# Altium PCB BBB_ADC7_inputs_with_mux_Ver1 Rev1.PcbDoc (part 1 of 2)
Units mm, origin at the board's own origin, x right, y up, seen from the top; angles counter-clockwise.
Board outline 219.96 x 100 mm, 2 copper layers (TopLayer, BottomLayer), stack 1.571 mm thick; 181 components, 118 nets, 709 pads, 266 vias.
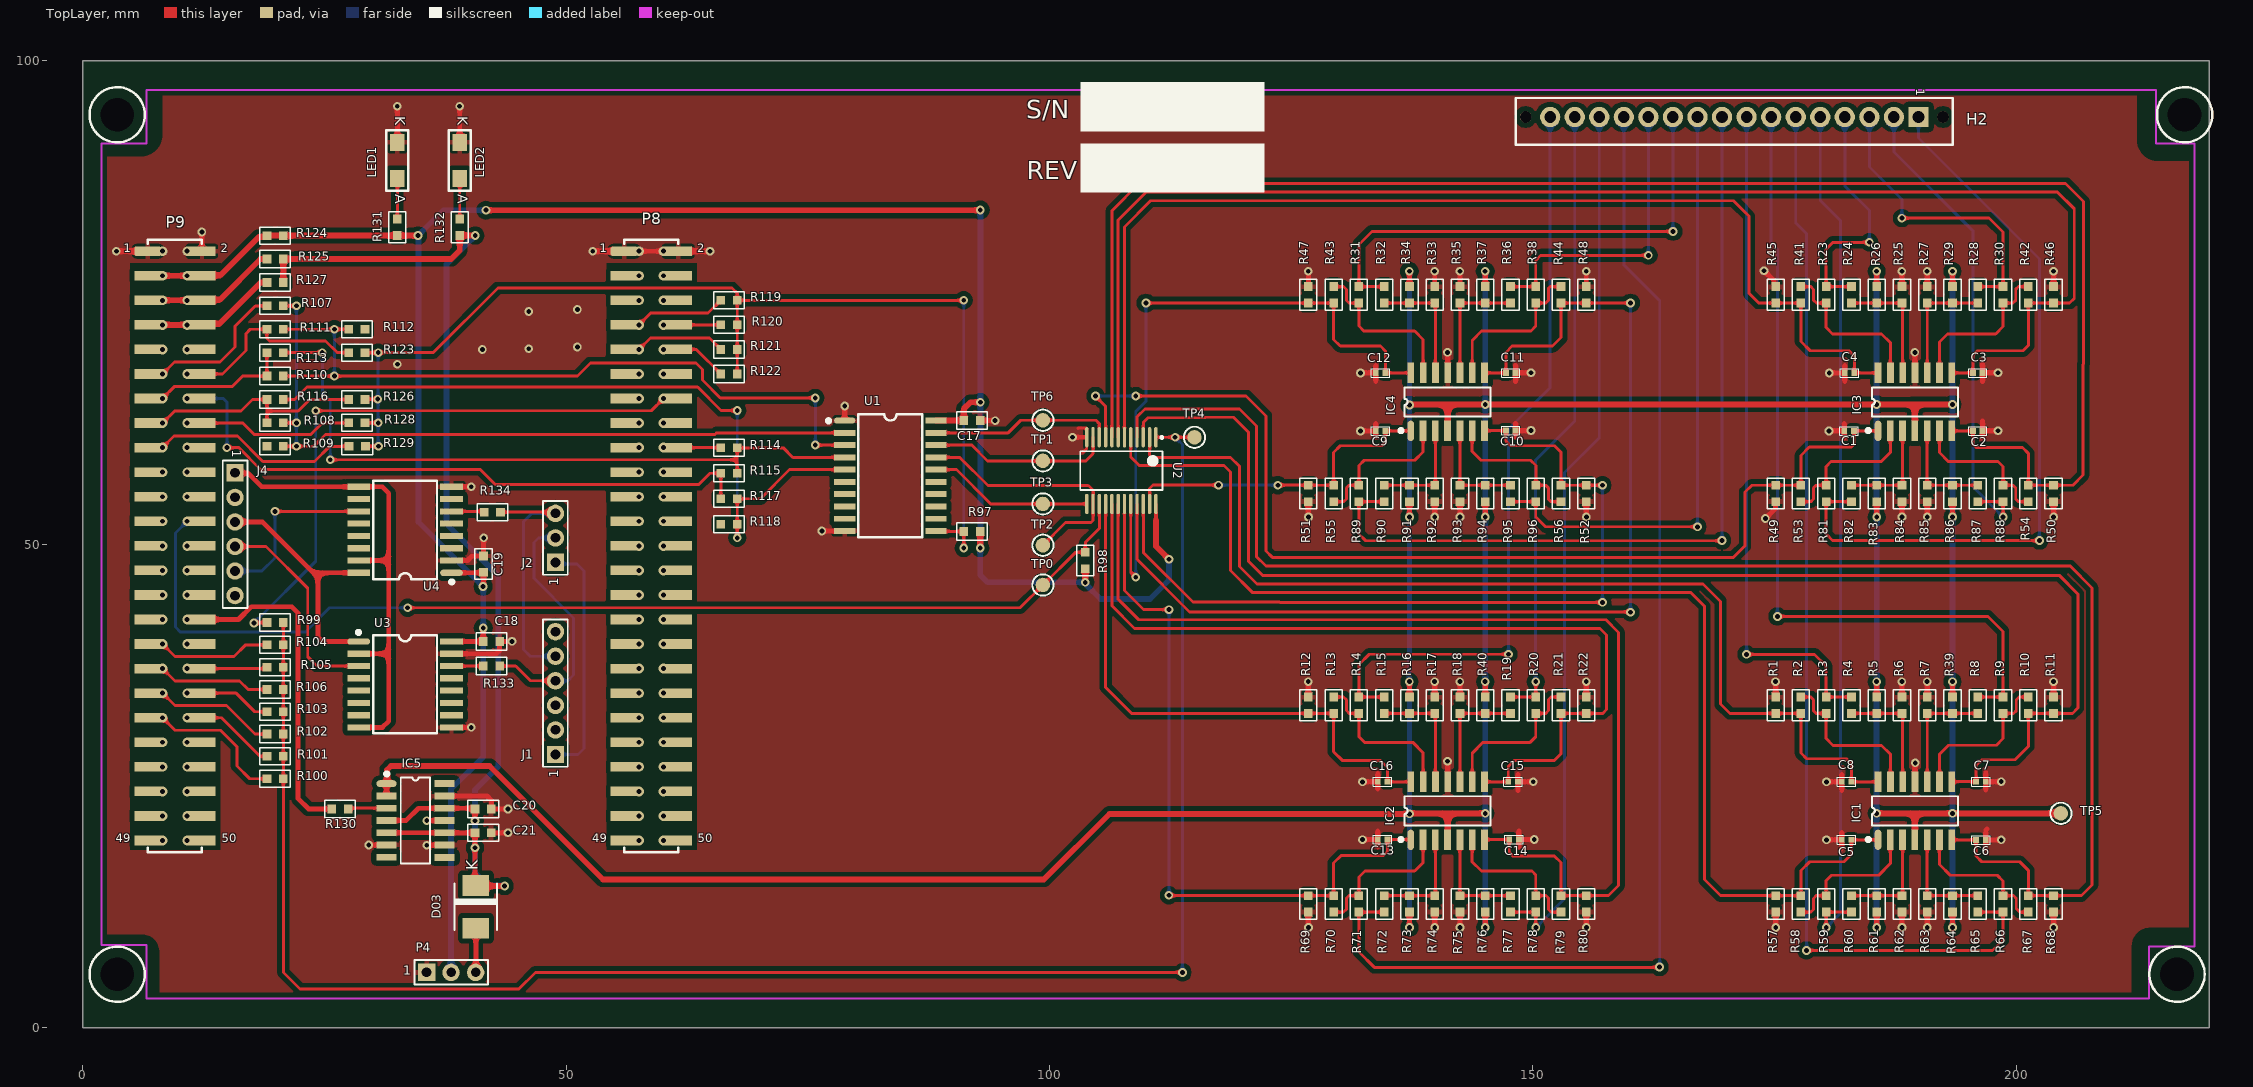
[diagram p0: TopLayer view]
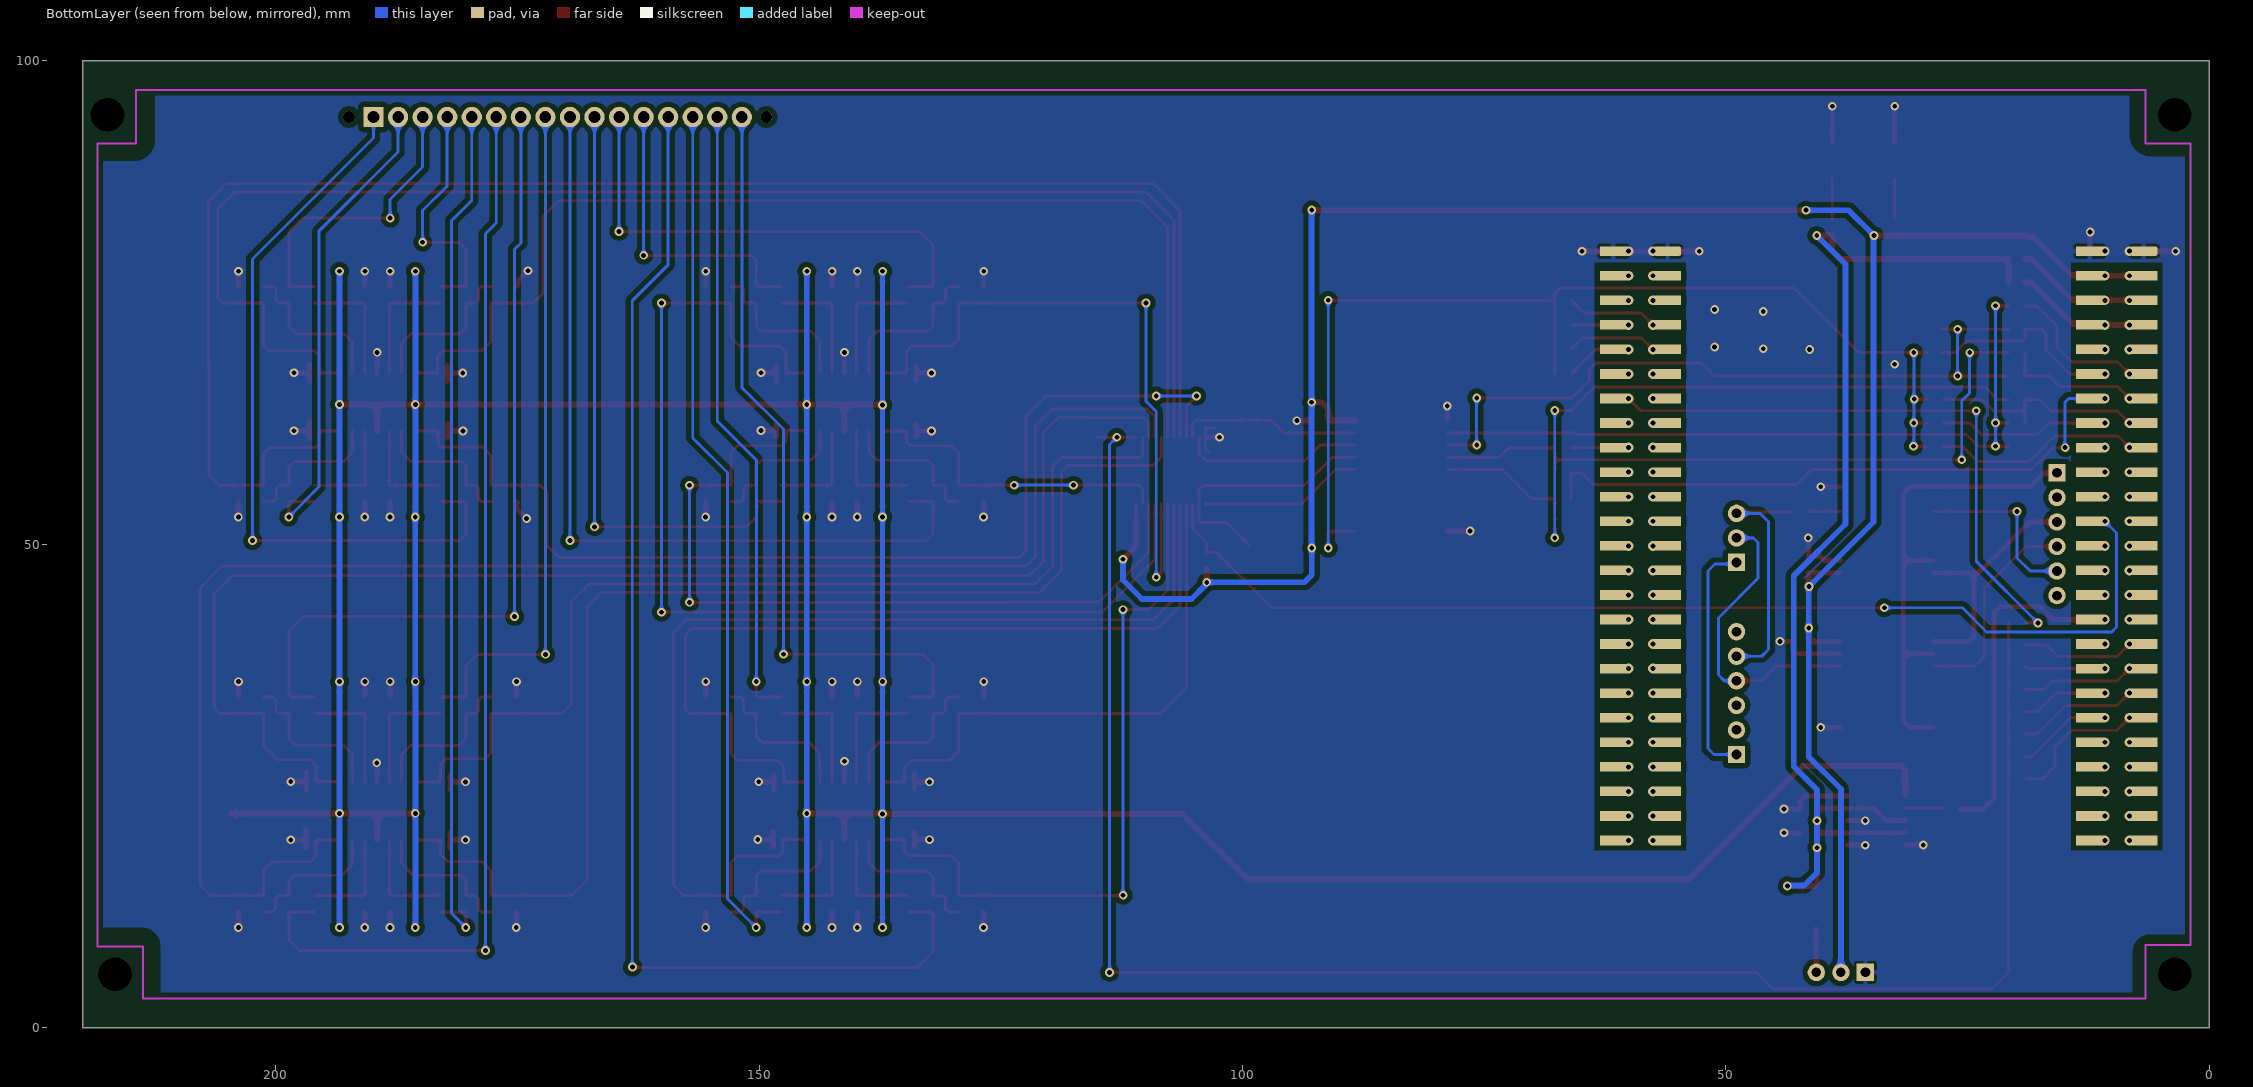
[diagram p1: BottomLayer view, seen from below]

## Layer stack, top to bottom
TopSolder: solder mask 0.0102, Solder Resist, Dk 3.5
TopLayer: signal copper 0.0356
Dielectric1: core 1.5, FR-4, Dk 4.8
BottomLayer: signal copper 0.0356
BottomSolder: solder mask 0.0102, Solder Resist, Dk 3.5

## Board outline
0,0 219.964,0 219.964,100 0,100

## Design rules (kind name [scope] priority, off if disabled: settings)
AssemblyTestPointUsage AssemblyTestPointUsage_1 [All] p2:
AssemblyTestpoint AssemblyTestpoint_1 [All] p2: testpointundercomponent=TRUE minsize=1.016 maxsize=2.54 preferedsize=1.524 minholesize=0 maxholesize=1.016 preferedholesize=0.813 testpointgrid=0.025 usegrid=TRUE gridtolerance=0 allowsidetop=TRUE allowsidebottom=TRUE
Clearance Clearance_1 [All vs InPolygon] p1: gap=0.508 ignorepadtopadclearanceinfootprint=FALSE
Clearance [All] p2: gap=0.254 ignorepadtopadclearanceinfootprint=FALSE
FabricationTestPointUsage TestPointUsage [All] p2: valid=0 allowmultiple=FALSE
FabricationTestpoint Testpoint [All] p2: side=3 testpointundercomponent=TRUE minsize=1.016 maxsize=2.54 preferedsize=1.524 minholesize=0.508 maxholesize=1.016 preferedholesize=0.813 testpointgrid=0.025 allowsidetop=TRUE allowsidebottom=TRUE usegrid=TRUE gridtolerance=0
FanoutControl Fanout_LCC [IsLCC] p1: bgadir=Out bgaviamode=Centered fanoutstyle=Auto fanoutdirection=Alternating viagrid=0.025 // Fanout_LCC (Default Rule)
FanoutControl Fanout_BGA [IsBGA] p2: bgadir=Out bgaviamode=Centered fanoutstyle=Auto fanoutdirection=Alternating viagrid=0.025 // Fanout_BGA (Default Rule)
FanoutControl Fanout_Small [(CompPinCount < 5)] p3: bgadir=Out bgaviamode=Centered fanoutstyle=Auto fanoutdirection=OutThenIn viagrid=0.025 // Fanout_Small (Default Rule)
FanoutControl Fanout_SOIC [IsSOIC] p4: bgadir=Out bgaviamode=Centered fanoutstyle=Auto fanoutdirection=Alternating viagrid=0.025 // Fanout_SOIC (Default Rule)
FanoutControl Fanout_BGA_1 [IsBGA] p6: bgadir=Out bgaviamode=Centered fanoutstyle=Auto fanoutdirection=Alternating viagrid=0.025 // Fanout_BGA (Default Rule)
FanoutControl Fanout_LCC_1 [IsLCC] p7: bgadir=Out bgaviamode=Centered fanoutstyle=Auto fanoutdirection=Alternating viagrid=0.025 // Fanout_LCC (Default Rule)
FanoutControl Fanout_SOIC_1 [IsSOIC] p8: bgadir=Out bgaviamode=Centered fanoutstyle=Auto fanoutdirection=Alternating viagrid=0.025 // Fanout_SOIC (Default Rule)
FanoutControl Fanout_Small_1 [(CompPinCount < 5)] p9: bgadir=Out bgaviamode=Centered fanoutstyle=Auto fanoutdirection=OutThenIn viagrid=0.025 // Fanout_Small (Default Rule)
FanoutControl Fanout_Default_1 [All] p10: bgadir=Out bgaviamode=Centered fanoutstyle=Auto fanoutdirection=Alternating viagrid=0.025 // Fanout_Default (Default Rule)
Height Height_1 [All] p2: minheight=0 maxheight=25.4 prefheight=12.7
HoleSize [All] p1: absolutevalues=TRUE maxlimit=6 minlimit=0.1 maxpercent=80.000 minpercent=20.000
MinimumSolderMaskSliver [All] p1 off: minsoldermaskwidth=0.254
PolygonConnect PolygonConnect_1 [All] p1: thpad.connectstyle=Relief thpad.reliefconductorwidth=0.5 thpad.reliefentries=4 thpad.polygonreliefangle="90 Angle" thpad.airgapwidth=0.254 smdpad.connectstyle=Relief smdpad.reliefconductorwidth=0.5 smdpad.reliefentries=4 smdpad.polygonreliefangle="90 Angle" smdpad.airgapwidth=0.254 via.connectstyle=Direct via.reliefconductorwidth=0.5 via.reliefentries=4 via.polygonreliefangle="90 Angle" via.airgapwidth=0.254
RoutingVias [All] p1: holewidth=0.5 width=0.9 viastyle="Through Hole" minholewidth=0.1 minwidth=0.45 maxholewidth=0.5 maxwidth=0.9
SilkToSilkClearance [All] p1: silktosilkclearance=0.15
SilkToSolderMaskClearance [IsPad] p1 off: minsilkscreentomaskgap=0.254 clearancetoexposedcopper=TRUE
SolderMaskExpansion [All] p1: expansion=0.102
Width [All] p1: maxlimit=5 minlimit=0.15 preferedwidth=0.3
22 further rules are at their usual default settings.

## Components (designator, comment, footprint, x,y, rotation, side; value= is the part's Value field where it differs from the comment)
C1 "CAPACITOR NONPOLAR SMT" C0402 182.718,61.719 r180 top
C2 "CAPACITOR NONPOLAR SMT" C0402 196.025,61.719 r0 top
C3 "CAPACITOR NONPOLAR SMT" C0402 196.025,67.719 r0 top
C4 "CAPACITOR NONPOLAR SMT" C0402 182.756,67.712 r180 top
C5 "CAPACITOR NONPOLAR SMT" C0402 182.456,19.416 r180 top
C6 "CAPACITOR NONPOLAR SMT" C0402 196.356,19.402 r0 top
C7 "CAPACITOR NONPOLAR SMT" C0402 196.356,25.428 r0 top
C8 "CAPACITOR NONPOLAR SMT" C0402 182.456,25.416 r180 top
C9 "CAPACITOR NONPOLAR SMT" C0402 134.256,61.712 r180 top
C10 "CAPACITOR NONPOLAR SMT" C0402 147.714,61.748 r0 top
C11 "CAPACITOR NONPOLAR SMT" C0402 147.714,67.719 r0 top
C12 "CAPACITOR NONPOLAR SMT" C0402 134.256,67.719 r180 top
C13 "CAPACITOR NONPOLAR SMT" C0402 134.462,19.444 r180 top
C14 "CAPACITOR NONPOLAR SMT" C0402 148.056,19.444 r0 top
C15 "CAPACITOR NONPOLAR SMT" C0402 147.956,25.416 r0 top
C16 "CAPACITOR NONPOLAR SMT" C0402 134.462,25.416 r180 top
C17 "4.7uF, 10V" C0603 91.985,62.788 r0 top
C18 "4.7uF, 10V" C0603 42.266,39.929 r0 top
C19 "4.7uF, 10V" C0603 41.456,47.932 r90 top
C20 "100nF" C0603 41.416,22.606 r0 top
C21 "4.7uF / 10V" C0603 41.416,20.137 r0 top
D03 "1.5A, PIV 1KV" DIODE_DO-214AA(SMB) 40.665,12.471 r90 top
H2 "connector 16 pin male_ stright" "16 PIN MALE STRIGHT" 170.84,94.183 r180 top
IC1 "OPamp" SOIC-14 189.522,22.416 r0 top
IC2 "OPamp" SOIC-14 141.186,22.416 r0 top
IC3 "OPamp" SOIC-14 189.522,64.719 r0 top
IC4 "OPamp" SOIC-14 141.186,64.719 r0 top
IC5 "OPamp" SOIC-14 34.417,21.412 r270 top
J1 "Header 6" HDR1X6 48.895,28.245 r90 top
J2 "Header 3" HDR1X3 48.895,48.108 r90 top
J4 "Header 6" HDR1X6 15.748,57.379 r270 top locked
LED1 "LED" "0537, LED, 1206" 32.537,89.687 r270 top
LED2 "LED" "0537, LED, 1206" 38.996,89.687 r270 top
P4 "Header 3" HDR1X3 35.56,5.703 r0 top
P8 "Header 20X2" BBBHEADERNOHOLE 58.801,79.035 r180 top locked
P9 "Header 20X2" BBBHEADERNOHOLE 9.525,79.035 r180 top locked
R1 "Resistor SMD 0603, 100 k Ohm, +/-5%, 1/10W" 0603 175.114,33.338 r90 top
R2 "Resistor SMD 0603, 1.5 k Ohm, +/-5%, 1/10W" 0603 177.728,33.338 r90 top
R3 "Resistor SMD 0603, 9.1 k Ohm, +/-5%, 1/10W" 0603 180.342,33.338 r90 top
R4 "open" 0603 182.956,33.338 r90 top
R5 "Resistor SMD 0603, 6.8 k Ohm, +/-1%, 1/10W" 0603 185.57,33.338 r90 top
R6 "Resistor SMD 0603, 4.7 k Ohm, +/-5%, 1/10W" 0603 188.183,33.338 r90 top
R7 "Resistor SMD 0603, 4.7 k Ohm, +/-5%, 1/10W" 0603 190.797,33.338 r90 top
R8 "open" 0603 196.025,33.338 r90 top
R9 "Resistor SMD 0603, 9.1 k Ohm, +/-5%, 1/10W" 0603 198.639,33.338 r270 top
R10 "Resistor SMD 0603, 1.5 k Ohm, +/-5%, 1/10W" 0603 201.253,33.338 r90 top
R11 "Resistor SMD 0603, 100 k Ohm, +/-5%, 1/10W" 0603 203.867,33.338 r90 top
R12 "Resistor SMD 0603, 100 k Ohm, +/-5%, 1/10W" 0603 126.778,33.338 r90 top
R13 "Resistor SMD 0603, 1.5 k Ohm, +/-5%, 1/10W" 0603 129.391,33.338 r90 top
R14 "Resistor SMD 0603, 9.1 k Ohm, +/-5%, 1/10W" 0603 132.005,33.338 r90 top
R15 "open" 0603 134.619,33.338 r90 top
R16 "Resistor SMD 0603, 6.8 k Ohm, +/-1%, 1/10W" 0603 137.233,33.338 r90 top
R17 "Resistor SMD 0603, 4.7 k Ohm, +/-5%, 1/10W" 0603 139.847,33.338 r90 top
R18 "Resistor SMD 0603, 4.7 k Ohm, +/-5%, 1/10W" 0603 142.461,33.338 r90 top
R19 "open" 0603 147.689,33.338 r90 top
R20 "Resistor SMD 0603, 9.1 k Ohm, +/-5%, 1/10W" 0603 150.303,33.338 r270 top
R21 "Resistor SMD 0603, 1.5 k Ohm, +/-5%, 1/10W" 0603 152.916,33.338 r90 top
R22 "Resistor SMD 0603, 100 k Ohm, +/-5%, 1/10W" 0603 155.53,33.338 r90 top
R23 "Resistor SMD 0603, 9.1 k Ohm, +/-5%, 1/10W" 0603 180.342,75.794 r90 top
R24 "OPEN" 0603 182.956,75.794 r90 top
R25 "Resistor SMD 0603, 4.7 k Ohm, +/-5%, 1/10W" 0603 188.183,75.794 r90 top
R26 "Resistor SMD 0603, 6.8 k Ohm, +/-1%, 1/10W" 0603 185.57,75.794 r90 top
R27 "Resistor SMD 0603, 4.7 k Ohm, +/-5%, 1/10W" 0603 190.797,75.794 r90 top
R28 "OPEN" 0603 196.025,75.794 r90 top
R29 "Resistor SMD 0603, 6.8 k Ohm, +/-1%, 1/10W" 0603 193.411,75.794 r90 top
R30 "Resistor SMD 0603, 9.1 k Ohm, +/-5%, 1/10W" 0603 198.639,75.794 r270 top
R31 "Resistor SMD 0603, 9.1 k Ohm, +/-5%, 1/10W" 0603 132.005,75.794 r90 top
R32 "OPEN" 0603 134.619,75.794 r90 top
R33 "Resistor SMD 0603, 4.7 k Ohm, +/-5%, 1/10W" 0603 139.847,75.794 r90 top
R34 "Resistor SMD 0603, 6.8 k Ohm, +/-1%, 1/10W" 0603 137.233,75.794 r90 top
R35 "Resistor SMD 0603, 4.7 k Ohm, +/-5%, 1/10W" 0603 142.461,75.794 r90 top
R36 "OPEN" 0603 147.689,75.794 r90 top
R37 "Resistor SMD 0603, 6.8 k Ohm, +/-1%, 1/10W" 0603 145.075,75.794 r90 top
R38 "Resistor SMD 0603, 9.1 k Ohm, +/-5%, 1/10W" 0603 150.303,75.794 r270 top
R39 "Resistor SMD 0603, 6.8 k Ohm, +/-1%, 1/10W" 0603 193.411,33.338 r90 top
R40 "Resistor SMD 0603, 6.8 k Ohm, +/-1%, 1/10W" 0603 145.075,33.338 r90 top
R41 "Resistor SMD 0603, 1.5 k Ohm, +/-5%, 1/10W" 0603 177.728,75.794 r90 top
R42 "Resistor SMD 0603, 1.5 k Ohm, +/-5%, 1/10W" 0603 201.253,75.794 r270 top
R43 "Resistor SMD 0603, 1.5 k Ohm, +/-5%, 1/10W" 0603 129.391,75.794 r90 top
R44 "Resistor SMD 0603, 1.5 k Ohm, +/-5%, 1/10W" 0603 152.916,75.794 r270 top
R45 "Resistor SMD 0603, 100 k Ohm, +/-5%, 1/10W" 0603 175.114,75.794 r90 top
R46 "Resistor SMD 0603, 100 k Ohm, +/-5%, 1/10W" 0603 203.867,75.794 r90 top
R47 "Resistor SMD 0603, 100 k Ohm, +/-5%, 1/10W" 0603 126.778,75.794 r90 top
R48 "Resistor SMD 0603, 100 k Ohm, +/-5%, 1/10W" 0603 155.53,75.794 r90 top
R49 "Resistor SMD 0603, 100 k Ohm, +/-5%, 1/10W" 0603 175.114,55.245 r270 top
R50 "Resistor SMD 0603, 100 k Ohm, +/-5%, 1/10W" 0603 203.867,55.245 r270 top
R51 "Resistor SMD 0603, 100 k Ohm, +/-5%, 1/10W" 0603 126.778,55.245 r270 top
R52 "Resistor SMD 0603, 100 k Ohm, +/-5%, 1/10W" 0603 155.53,55.245 r270 top
R53 "Resistor SMD 0603, 1.5 k Ohm, +/-5%, 1/10W" 0603 177.728,55.245 r270 top
R54 "Resistor SMD 0603, 1.5 k Ohm, +/-5%, 1/10W" 0603 201.253,55.245 r90 top
R55 "Resistor SMD 0603, 1.5 k Ohm, +/-5%, 1/10W" 0603 129.391,55.245 r270 top
R56 "Resistor SMD 0603, 1.5 k Ohm, +/-5%, 1/10W" 0603 152.916,55.245 r90 top
R57 "Resistor SMD 0603, 100 k Ohm, +/-5%, 1/10W" 0603 175.114,12.789 r90 top
R58 "Resistor SMD 0603, 1.5 k Ohm, +/-5%, 1/10W" 0603 177.728,12.789 r90 top
R59 "Resistor SMD 0603, 9.1 k Ohm, +/-5%, 1/10W" 0603 180.342,12.789 r90 top
R60 "open" 0603 182.956,12.789 r90 top
R61 "Resistor SMD 0603, 6.8 k Ohm, +/-1%, 1/10W" 0603 185.57,12.789 r90 top
R62 "Resistor SMD 0603, 4.7 k Ohm, +/-5%, 1/10W" 0603 188.183,12.789 r90 top
R63 "Resistor SMD 0603, 4.7 k Ohm, +/-5%, 1/10W" 0603 190.797,12.789 r90 top
R64 "Resistor SMD 0603, 6.8 k Ohm, +/-1%, 1/10W" 0603 193.411,12.789 r90 top
R65 "open" 0603 196.025,12.789 r90 top
R66 "Resistor SMD 0603, 9.1 k Ohm, +/-5%, 1/10W" 0603 198.639,12.789 r90 top
R67 "Resistor SMD 0603, 1.5 k Ohm, +/-5%, 1/10W" 0603 201.253,12.789 r270 top
R68 "Resistor SMD 0603, 100 k Ohm, +/-5%, 1/10W" 0603 203.867,12.789 r270 top
R69 "Resistor SMD 0603, 100 k Ohm, +/-5%, 1/10W" 0603 126.778,12.789 r90 top
R70 "Resistor SMD 0603, 1.5 k Ohm, +/-5%, 1/10W" 0603 129.391,12.789 r90 top
R71 "Resistor SMD 0603, 9.1 k Ohm, +/-5%, 1/10W" 0603 132.005,12.789 r90 top
R72 "open" 0603 134.619,12.789 r90 top
R73 "Resistor SMD 0603, 6.8 k Ohm, +/-1%, 1/10W" 0603 137.233,12.789 r90 top
R74 "Resistor SMD 0603, 4.7 k Ohm, +/-5%, 1/10W" 0603 139.847,12.789 r90 top
R75 "Resistor SMD 0603, 4.7 k Ohm, +/-5%, 1/10W" 0603 142.461,12.789 r90 top
R76 "Resistor SMD 0603, 6.8 k Ohm, +/-1%, 1/10W" 0603 145.075,12.789 r90 top
R77 "open" 0603 147.689,12.789 r90 top
R78 "Resistor SMD 0603, 9.1 k Ohm, +/-5%, 1/10W" 0603 150.303,12.789 r90 top
R79 "Resistor SMD 0603, 1.5 k Ohm, +/-5%, 1/10W" 0603 152.916,12.789 r270 top
R80 "Resistor SMD 0603, 100 k Ohm, +/-5%, 1/10W" 0603 155.53,12.789 r270 top
R81 "Resistor SMD 0603, 9.1 k Ohm, +/-5%, 1/10W" 0603 180.342,55.245 r90 top
R82 "OPEN" 0603 182.956,55.245 r90 top
R83 "Resistor SMD 0603, 6.8 k Ohm, +/-1%, 1/10W" 0603 185.57,55.245 r90 top
R84 "Resistor SMD 0603, 4.7 k Ohm, +/-5%, 1/10W" 0603 188.183,55.245 r90 top
R85 "Resistor SMD 0603, 4.7 k Ohm, +/-5%, 1/10W" 0603 190.797,55.245 r90 top
R86 "Resistor SMD 0603, 6.8 k Ohm, +/-1%, 1/10W" 0603 193.411,55.245 r90 top
R87 "OPEN" 0603 196.025,55.245 r90 top
R88 "Resistor SMD 0603, 9.1 k Ohm, +/-5%, 1/10W" 0603 198.639,55.245 r90 top
R89 "Resistor SMD 0603, 9.1 k Ohm, +/-5%, 1/10W" 0603 132.005,55.245 r90 top
R90 "OPEN" 0603 134.619,55.245 r90 top
R91 "Resistor SMD 0603, 6.8 k Ohm, +/-1%, 1/10W" 0603 137.233,55.245 r90 top
R92 "Resistor SMD 0603, 4.7 k Ohm, +/-5%, 1/10W" 0603 139.847,55.245 r90 top
R93 "Resistor SMD 0603, 4.7 k Ohm, +/-5%, 1/10W" 0603 142.461,55.245 r90 top
R94 "Resistor SMD 0603, 6.8 k Ohm, +/-1%, 1/10W" 0603 145.075,55.245 r90 top
R95 "OPEN" 0603 147.689,55.245 r90 top
R96 "Resistor SMD 0603, 9.1 k Ohm, +/-5%, 1/10W" 0603 150.303,55.245 r90 top
R97 "" 0603 91.985,51.317 r0 top
R98 "1Kohm" 0603 103.705,48.314 r270 top
R99 "1Kohm" 0603 19.896,41.894 r0 top
R100 "1Kohm" 0603 19.896,25.736 r0 top
R101 "1Kohm" 0603 19.896,28.045 r0 top
R102 "1Kohm" 0603 19.896,30.353 r0 top
R103 "1Kohm" 0603 19.896,32.661 r0 top
R104 "1Kohm" 0603 19.896,39.586 r0 top
R105 "1Kohm" 0603 19.896,37.277 r0 top
R106 "1Kohm" 0603 19.896,34.969 r0 top
R107 "" 0603 19.896,74.651 r0 top
R108 "" 0603 19.896,62.543 r0 top
R109 "" 0603 19.896,60.122 r0 top
R110 "" 0603 19.896,67.386 r0 top
R111 "" 0603 19.896,72.229 r0 top
R112 "" 0603 28.35,72.229 r180 top
R113 "" 0603 19.896,69.808 r0 top
R114 "" 0603 66.853,59.965 r0 top
R115 "" 0603 66.853,57.333 r0 top
R116 "" 0603 19.896,64.965 r0 top
R117 "" 0603 66.853,54.702 r0 top
R118 "" 0603 66.853,52.07 r0 top
R119 "1Kohm" 0603 66.853,75.225 r180 top
R120 "1Kohm" 0603 66.853,72.685 r180 top
R121 "1Kohm" 0603 66.853,70.145 r180 top
R122 "1Kohm" 0603 66.853,67.605 r180 top
R123 "1Kohm" 0603 28.35,69.808 r180 top
R124 "Resistor SMD 0603, 0 Ohm, +/-5%, 1/10W" 0603 19.896,81.915 r0 top
R125 "Resistor SMD 0603, 0 Ohm, +/-5%, 1/10W" 0603 19.896,79.494 r180 top
R126 "1Kohm" 0603 28.35,64.965 r180 top
R127 "Resistor SMD 0603, 0 Ohm, +/-5%, 1/10W" 0603 19.896,77.072 r180 top
R128 "1Kohm" 0603 28.35,62.543 r180 top
R129 "1Kohm" 0603 28.386,60.122 r180 top
R130 "Resistor SMD 0603, 0 Ohm, +/-5%, 1/10W" 0603 26.594,22.606 r0 top
R131 "Resistor SMD 0603, 4.7 k Ohm, +/-5%, 1/10W" 0603 32.537,82.779 r270 top
R132 "Resistor SMD 0603, 4.7 k Ohm, +/-5%, 1/10W" 0603 38.996,82.779 r270 top
R133 "Resistor SMD 0603, 0 Ohm, +/-5%, 1/10W" 0603 42.266,37.389 r0 top
R134 "Resistor SMD 0603, 0 Ohm, +/-5%, 1/10W" 0603 42.367,53.315 r0 top
TP0 "TEST PAD" TP 99.316,45.775 r0 top
TP1 "TEST PAD" TP 99.316,58.609 r0 top
TP2 "TEST PAD" TP 99.316,49.887 r0 top
TP3 "TEST PAD" TP 99.316,54.159 r0 top
TP4 "TEST PAD" TP 114.998,61.046 r0 top
TP5 "TEST PAD" TP 204.625,22.15 r180 top
TP6 "TEST PAD" TP 99.316,62.816 r0 top
U1 "74ACT573SJ" SOL-20 83.538,57.073 r0 top
U2 "4067" SSOP-24 107.43,57.609 r270 top
U3 "ISO7640" SOIC-16 33.339,35.484 r270 top
U4 "ISO7640" SOIC-16 33.339,51.486 r90 top

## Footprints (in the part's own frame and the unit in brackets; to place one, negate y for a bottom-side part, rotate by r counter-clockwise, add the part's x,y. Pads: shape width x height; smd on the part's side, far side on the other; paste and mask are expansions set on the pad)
"16 PIN MALE STRIGHT" [mm]
  round 1.2 hole 1.2 unplated: 0(-21.59,0) 0(21.59,0)
  rect 2.1x2.1 hole 1.2: 1(-19.05,0)
  round 2.1 hole 1.2: 2(-16.51,0) 3(-13.97,0) 4(-11.43,0) 5(-8.89,0) 6(-6.35,0) 7(-3.81,0) 8(-1.27,0) 9(1.27,0) 10(3.81,0) 11(6.35,0) 12(8.89,0) 13(11.43,0) 14(13.97,0) 15(16.51,0) 16(19.05,0)
  silkscreen extent -22.61,-1.97 22.61,2.88, body extent -22.58,-1.96 22.65,2.89, height 7.1
"0537, LED, 1206" [mm]
  rect 1.75x1.5 smd: A(1.875,0) K(-1.875,0)
  silkscreen extent -3.11,-1.14 3.14,1.12, body extent -1.6,-0.8 1.6,0.8, height 1.52
0603 [mm]
  rect 0.9x0.9 smd: 1(-0.85,0) 2(0.85,0)
  silkscreen extent -1.59,-0.89 1.59,0.89, body extent -0.85,-0.4 0.85,0.4, height 0.56
BBBHEADERNOHOLE [mm]
  rrect50% 2.8x1 smd far side: 1(2.77,-1.27)
  rrect50% 2.8x1 smd: 1(2.8,-1.27)
  rect 2.8x1 smd far side: 2(-2.83,-1.27) 3(2.77,1.27) 4(-2.83,1.27) 5(2.77,3.81) 6(-2.83,3.81) 7(2.77,6.35) 8(-2.83,6.35) 9(2.77,8.89) 10(-2.83,8.89) 11(2.77,11.43) 12(-2.83,11.43) 13(2.77,13.97) 14(-2.83,13.97) 15(2.77,16.51) 16(-2.83,16.51) 17(2.77,19.05) 18(-2.83,19.05) 19(2.77,21.59) 20(-2.83,21.59) 21(2.77,24.13) 22(-2.83,24.13) 23(2.77,26.67) 24(-2.83,26.67) 25(2.77,29.21) 26(-2.83,29.21) 27(2.77,31.75) 28(-2.83,31.75) 29(2.77,34.29) 30(-2.83,34.29) 31(2.77,36.83) 32(-2.83,36.83) 33(2.77,39.37) 34(-2.83,39.37) 35(2.77,41.91) 36(-2.83,41.91) 37(2.77,44.45) 38(-2.83,44.45) 39(2.77,46.99) 40(-2.83,46.99) 41(2.77,49.53) 42(-2.83,49.53) 43(2.77,52.07) 44(-2.83,52.07) 45(2.77,54.61) 46(-2.83,54.61) 47(2.77,57.15) 48(-2.83,57.15) 49(2.77,59.69) 50(-2.83,59.69)
  rect 2.8x1 smd: 2(-2.8,-1.27) 3(2.8,1.27) 4(-2.8,1.27) 5(2.8,3.81) 6(-2.8,3.81) 7(2.8,6.35) 8(-2.8,6.35) 9(2.8,8.89) 10(-2.8,8.89) 11(2.8,11.43) 12(-2.8,11.43) 13(2.8,13.97) 14(-2.8,13.97) 15(2.8,16.51) 16(-2.8,16.51) 17(2.8,19.05) 18(-2.8,19.05) 19(2.8,21.59) 20(-2.8,21.59) 21(2.8,24.13) 22(-2.8,24.13) 23(2.8,26.67) 24(-2.8,26.67) 25(2.8,29.21) 26(-2.8,29.21) 27(2.8,31.75) 28(-2.8,31.75) 29(2.8,34.29) 30(-2.8,34.29) 31(2.8,36.83) 32(-2.8,36.83) 33(2.8,39.37) 34(-2.8,39.37) 35(2.8,41.91) 36(-2.8,41.91) 37(2.8,44.45) 38(-2.8,44.45) 39(2.8,46.99) 40(-2.8,46.99) 41(2.8,49.53) 42(-2.8,49.53) 43(2.8,52.07) 44(-2.8,52.07) 45(2.8,54.61) 46(-2.8,54.61) 47(2.8,57.15) 48(-2.8,57.15) 49(2.8,59.69) 50(-2.8,59.69)
  silkscreen extent -2.79,-2.46 2.81,60.88
C0402 [mm] "C0402"
  rect 0.6x0.6 smd: 1(-0.5,0) 2(0.5,0)
  silkscreen extent -0.95,-0.45 0.95,0.45, body extent -0.51,-0.25 0.51,0.25, height 0.51
C0603 [mm]
  rect 0.9x0.9 smd: 1(-0.85,0) 2(0.85,0)
  silkscreen extent -1.59,-0.89 1.59,0.89, body extent -0.8,-0.4 0.8,0.4, height 0.3
DIODE_DO-214AA(SMB) [mm]
  rect 2.159x2.743 smd: 1(-2.21,0) 2(2.21,0)
  silkscreen extent -2.41,-2.2 2.42,2.2, body extent -2.75,-1.95 2.75,1.95, height 2.45
HDR1X3 [mm]
  rect 1.8x1.8 hole 1: 1(0,0)
  round 1.8 hole 1: 2(2.54,0) 3(5.08,0)
  silkscreen extent -1.27,-1.27 6.35,1.27, body extent -1.24,-1.22 6.38,1.32, height 9.07
HDR1X6 [mm] "Connector; Header; 6 Position"
  rect 1.8x1.8 hole 1: 1(0,0)
  round 1.8 hole 1: 2(2.54,0) 3(5.08,0) 4(7.62,0) 5(10.16,0) 6(12.7,0)
  silkscreen extent -1.27,-1.27 13.97,1.27, body extent -1.27,-1.27 13.97,1.27, height 9.07
SOIC-14 [mm]
  oval 0.7x2.1 smd: 1(-3.815,-3)
  rect 0.7x2.1 smd: 2(-2.545,-3) 3(-1.275,-3) 4(-0.005,-3) 5(1.265,-3) 6(2.535,-3) 7(3.805,-3) 8(3.815,3) 9(2.545,3) 10(1.275,3) 11(0.005,3) 12(-1.265,3) 13(-2.535,3) 14(-3.815,3)
  silkscreen extent -4.95,-3.09 4.44,1.51, body extent -4.35,-3.07 4.35,3.07, height 1.88
SOIC-16 [mm]
  oval 0.64x2.35 smd: 1(-4.445,-4.8)
  rect 0.64x2.35 smd: 2(-3.175,-4.8) 3(-1.905,-4.8) 4(-0.635,-4.8) 5(0.635,-4.8) 6(1.905,-4.8) 7(3.175,-4.8) 8(4.445,-4.8) 9(4.445,4.8) 10(3.175,4.8) 11(1.905,4.8) 12(0.635,4.8) 13(-0.635,4.8) 14(-1.905,4.8) 15(-3.175,4.8) 16(-4.445,4.8)
  silkscreen extent -5.51,-4.94 5.05,3.3, body extent -5.17,-5.15 5.16,5.16, height 2.48
SOL-20 [mm]
  oval 2.2x0.61 smd: 1(-4.726,5.715)
  rect 2.2x0.61 smd: 2(-4.726,4.445) 3(-4.726,3.175) 4(-4.726,1.905) 5(-4.726,0.635) 6(-4.726,-0.635) 7(-4.726,-1.905) 8(-4.726,-3.175) 9(-4.726,-4.445) 10(-4.726,-5.715) 11(4.726,-5.715) 12(4.726,-4.445) 13(4.726,-3.175) 14(4.726,-1.905) 15(4.726,-0.635) 16(4.726,0.635) 17(4.726,1.905) 18(4.726,3.175) 19(4.726,4.445) 20(4.726,5.715)
  silkscreen extent -6.51,-6.35 3.3,6.35
SSOP-24 [mm]
  oval 2.1x0.35 smd: 1(-3.45,3.575) 2(-3.45,2.925) 3(-3.45,2.275) 4(-3.45,1.625) 5(-3.45,0.975) 6(-3.45,0.325) 7(-3.45,-0.325) 8(-3.45,-0.975) 9(-3.45,-1.625) 10(-3.45,-2.275) 11(-3.45,-2.925) 12(-3.45,-3.575) 13(3.45,-3.575) 14(3.45,-2.925) 15(3.45,-2.275) 16(3.45,-1.625) 17(3.45,-0.975) 18(3.45,-0.325) 19(3.45,0.325) 20(3.45,0.975) 21(3.45,1.625) 22(3.45,2.275) 23(3.45,2.925) 24(3.45,3.575)
  silkscreen extent -3.56,-4.25 2,4.31, body extent -2.8,-4.25 2.8,4.25, height 2
TP [mm]
  round 1.5 smd paste-2: 1(0,0)
  silkscreen extent -1.1,-1.1 1.1,1.1

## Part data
C1 C2 C3 C4 C5 C6 C7 C8 C9 C10 C11 C12 C13 C14 C15 C16: library part BCS22A-102, "Capacitor ceramic, SMD 0402, 1 nF, +/-10%, 50 V dc", Capacitance=1, Dielectric=X7R, Mfr Name=YAGEO, Package=0402, Tolerance (%)=+/-10%, Units of Capacitance=nF, Units of Voltage="V dc", Value(Farad)=1n, Voltage Rating=50
C17 C18 C19 C21: library part BCS129-475, "Capacitor ceramic, SMD 0603, 4.7 uF, +/-10%, 10 V dc", Capacitance=4.7, Dielectric=X5R, Mfr Name=KEMET, Package=0603, Tolerance (%)=+/-10%, Units of Capacitance=uF, Units of Voltage="V dc", Voltage Rating=10
C20: library part BCS129-104, "Capacitor ceramic, SMD 0603, 100 nF, +/-10%, 16 V dc", Capacitance=100, Dielectric=X7R, Mfr Name=KEMET, Package=0603, Tolerance (%)=+/-10%, Units of Capacitance=nF, Units of Voltage="V dc", Value(Farad)=100n, Voltage Rating=16
D03: library part BDS334-001, "Diode high voltage, SMD DO-214AA, If 1.5 A, PIV 1 kV", Average Forward Current=1.5, Mfr Name=VISHAY, Package=DO-214AA, PackageDocument=Sep-1996, Peak Inverse Voltage=1, Units of Current=A, Units of Voltage=kV
IC1 IC2 IC3 IC4: SMLPARTNO=BIS114-020
IC5: SMLPPARTNO=BIS114-020
J1 J4: "Header, 6-Pin"
J2 P4: "Header, 3-Pin"
LED1 LED2: library part BDS461-001, "Optoelectronic LED, SMD 1206, red colour", LED Colour=Red, Mfr Name="AVAGO TECHNOLOGIES", Package=1206
P8 P9: "Header, 20-Pin, Dual row"
R1 R11 R12 R22 R45 R46 R47 R48 R49 R50 R51 R52 R57 R68 R69 R80: library part BRS133-473, Mfr Name=VISHAY, Package=0603, Power Rating=1/10W, SMLPARTNO=BRS131-104, Tempco1=0.0002, Tolerance=+/-5%, Unit Of Resistance="k Ohm", Value(ohm)=100
R2 R13 R41 R42 R43 R44 R53 R54 R55 R56 R58 R67 R70 R79: library part BRS133-473, Mfr Name=VISHAY, Package=0603, Power Rating=1/10W, SMLPARTNO=BRS131-152, Tempco1=0.0002, Tolerance=+/-5%, Unit Of Resistance="k Ohm", Value(ohm)=1.5
R3 R9 R14 R20 R30 R38 R66 R78 R81 R88 R89 R96: library part BRS133-473, Mfr Name=VISHAY, Package=0603, Power Rating=1/10W, SMLPARTNO=BRS131-912, Tempco1=0.0002, Tolerance=+/-5%, Unit Of Resistance="k Ohm", Value(ohm)=9.1
R4 R8 R15 R19 R24 R28 R32 R36 R60 R72 R82 R87 R90 R95: library part BRS133-473, Mfr Name=VISHAY, Package=0603, Power Rating=1/10W, Tempco1=0.0002, Tolerance=+/-5%
R5 R16 R26 R34 R39 R40 R61 R64 R73 R76 R86 R94: library part BRS133-473, Mfr Name=VISHAY, Package=0603, Power Rating=1/10W, SMLPARTNO=BRS131-682, Tempco1=0.0002, Tolerance=+/-5%, Unit Of Resistance="k Ohm", Value(ohm)=6.5
R6 R7 R17 R18 R25 R27 R33 R35 R62 R63 R74 R75 R84 R85 R92 R93: library part BRS133-473, Mfr Name=VISHAY, Package=0603, Power Rating=1/10W, SMLPARTNO=BRS133-472, Tempco1=0.0002, Tolerance=+/-5%, Unit Of Resistance="k Ohm", Value(ohm)=4.7
R10 R21: library part BRS133-473, Mfr Name=VISHAY, Package=0603, Power Rating=1/10W, Resistance=47, SMLPARTNO=BRS131-152, Tempco1=0.0002, Tolerance=+/-5%, Unit Of Resistance="k Ohm", Value(ohm)=1.5
R23 R31: library part BRS133-473, Mfr Name=VISHAY, Package=0603, Power Rating=1/10W, Resistance=47, SMLPARTNO=BRS131-912, Tempco1=0.0002, Tolerance=+/-5%, Unit Of Resistance="k Ohm", Value(ohm)=9.1
R29 R37 R83 R91: library part BRS133-473, Mfr Name=VISHAY, Package=0603, Power Rating=1/10W, Resistance=47, SMLPARTNO=BRS131-682, Tempco1=0.0002, Tolerance=+/-5%, Unit Of Resistance="k Ohm", Value(ohm)=6.5
R59 R71: library part BRS133-473, Mfr Name=VISHAY, Package=0603, Power Rating=1/10W, SMLPARTNO=BRS133-902, Tempco1=0.0002, Tolerance=+/-5%, Unit Of Resistance="k Ohm", Value(ohm)=9.2
R65 R77: library part BRS133-473, Mfr Name=VISHAY, Package=0603, Power Rating=1/10W, Tempco1=0.0002, Tolerance=+/-5%, Unit Of Resistance="k Ohm"
R97 R107 R108 R109 R110 R111 R112 R113 R114 R115 R116 R117 R118: library part BRS132-472, "Resistor SMD 0603, 0 Ohm, +/-5%, 1/10W", Mfr Name=YAGEO, Package=0603, Power Rating=1/10W, Resistance=0, SMLPARTNO=BRS132-000, Tempco1=0.0001, Tolerance=+/-5%, Unit Of Resistance="k Ohm", Value(ohm)=4.7k
R98 R99 R100 R101 R102 R103 R104 R105 R106 R119 R120 R121 R122 R123 R126 R128 R129: library part BRS831-102, "Resistor SMD 0603, 1 k Ohm, +/-1%, 1/10W", Mfr Name=YAGEO, Package=0603, Power Rating=1/10W, Resistance=1, Tempco1=0.00005, Tolerance=+/-1%, Unit Of Resistance="k Ohm", Value(ohm)=1k
R124: library part BRS133-473, Mfr Name=VISHAY, Package=0603, Power Rating=1/10W, SMLPARTNO=BRS133-000, Tempco1=0.0002, Tolerance=+/-5%, Value(ohm)=0
R125 R127 R133 R134: library part BRS133-473, Mfr Name=VISHAY, Package=0603, Power Rating=1/10W, SMLPARTNO=BRS133-000, Tempco1=0.0002, Tolerance=+/-5%, Unit Of Resistance=Ohm, Value(ohm)=0
R130: library part BRS133-473, Mfr Name=VISHAY, Package=0603, Power Rating=1/10W, Resistance=47, SMLPARTNO=BRS133-000, Tempco1=0.0002, Tolerance=+/-5%, Unit Of Resistance=Ohm, Value(ohm)=0
R131 R132: library part BRS831-102, Mfr Name=YAGEO, Package=0603, Power Rating=1/10W, SMLPARTNO=BRS133-472, Tempco1=0.00005, Tolerance=+/-1%, Unit Of Resistance="k Ohm", Value(ohm)=4.7
U1: "Octal Latch with 3-State Output"
U2: library part MUX-74HC4067, "MUX-74HC4067"
U3 U4: library part BIS116-038, "IC digital isolator SMD SOIC-16, ISO7640", LED Colour="Not Applicable", Mfr Name="TEXAS INSTRUMENTS", Package=SOIC

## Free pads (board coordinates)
  round 1.27 hole 3.5: 1(3.556,94.412) 1(216.637,5.512) 1(217.424,94.412) 2(3.556,5.512)

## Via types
v1: diameter 0.9, hole 0.5, TopLayer to BottomLayer, tented both sides, 166 vias
v2: diameter 1.016, hole 0.508, TopLayer to BottomLayer, 100 vias

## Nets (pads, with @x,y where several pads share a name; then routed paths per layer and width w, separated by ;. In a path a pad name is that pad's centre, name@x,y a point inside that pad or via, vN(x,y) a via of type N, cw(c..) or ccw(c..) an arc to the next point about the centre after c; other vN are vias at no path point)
3.3V_PC: J4.3 U3.1 U4.16 | length 26.9
  TopLayer w0.5: J4.3@15.748,52.299 18.576,52.299 23.834,47.041 ; 24.802,47.041 24.318,46.557 ; U3.1@28.539,39.929 24.826,39.929 24.318,40.437 24.318,46.557 ; U4.16@28.539,47.041 23.834,47.041 ; 23.834,47.041 24.318,46.557
+1.8: IC1.4 IC2.4 IC3.4 IC4.4 IC5.1 IC5.2 R5.2 R16.2 R26.2 R29.2 R34.2 R37.2 R39.2 R40.2 R61.1 R64.1 R73.1 R76.1 R83.1 R86.1 R91.1 R94.1 TP5.1 | length 511.1
  TopLayer w0.3: v1(137.225,35.777) v1@137.233,35.769 ; v1(137.225,78.233) v1@137.233,78.225 ; v1@137.233,10.358 v1(137.241,10.35) ; v1@137.233,52.814 v1(137.241,52.806) ; v1(145.067,35.777) v1@145.075,35.769 ; v1(145.067,78.233) v1@145.075,78.225 ; v1@145.075,10.358 v1(145.083,10.35) ; v1@145.075,52.814 v1(145.083,52.806) ; v1(185.561,35.777) v1@185.57,35.769 ; v1(185.561,78.233) v1@185.57,78.225 ; v1@185.57,10.358 v1(185.578,10.35) ; v1@185.57,52.814 v1(185.578,52.806) ; v1(193.403,35.777) v1@193.411,35.769 ; v1(193.403,78.233) v1@193.411,78.225 ; v1@193.411,10.358 v1(193.419,10.35) ; v1@193.411,52.814 v1(193.419,52.806)
  TopLayer w0.5: IC5.2@31.417,23.957 IC5.1@31.417,25.227 ; v1@137.233,10.358 R73.1@137.233,11.939 ; R16.2@137.233,34.188 v1@137.233,35.769 ; v1@137.233,52.814 R91.1@137.233,54.395 ; R34.2@137.233,76.644 v1@137.233,78.225 ; v1@145.075,10.358 R76.1@145.075,11.939 ; R40.2@145.075,34.188 v1@145.075,35.769 ; v1@145.075,52.814 R94.1@145.075,54.395 ; R37.2@145.075,76.644 v1@145.075,78.225 ; v1@185.57,10.358 R61.1@185.57,11.939 ; R5.2@185.57,34.188 v1@185.57,35.769 ; v1@185.57,52.814 R83.1@185.57,54.395 ; R26.2@185.57,76.644 v1@185.57,78.225 ; v1@193.411,10.358 R64.1@193.411,11.939 ; R39.2@193.411,34.188 v1@193.411,35.769 ; v1@193.411,52.814 R86.1@193.411,54.395 ; R29.2@193.411,76.644 v1@193.411,78.225
  TopLayer w0.6: IC5.1@31.417,25.227 31.429,25.227 31.475,25.273 31.475,26.65 31.887,27.062 42.063,27.062 53.814,15.311 99.411,15.311 106.198,22.098 v1(137.241,22.098) 137.293,22.15 140.662,22.15 ; v1(137.241,64.402) 137.293,64.453 140.662,64.453 ; IC2.4@141.181,19.416 141.181,21.631 ; IC4.4@141.181,61.719 141.181,63.934 ; v1(145.083,22.15) 141.7,22.15 ; v1(185.561,22.15) 189.055,22.15 ; IC1.4@189.517,19.416 189.517,21.688 ; IC3.4@189.517,61.719 189.517,63.991 ; v1(193.403,64.453) 189.979,64.453 ; TP5.1@204.625,22.15 v1(193.403,22.15) 189.979,22.15 ; 140.662,22.15 141.7,22.15 ; 140.662,22.15 141.181,21.631 ; 140.662,64.453 141.7,64.453 ; 140.662,64.453 141.181,63.934 ; 141.181,21.631 141.7,22.15 ; 141.181,63.934 141.7,64.453 ; 141.7,64.453 v1(145.083,64.453) v1(185.561,64.453) 189.055,64.453 ; 189.055,22.15 189.979,22.15 ; 189.055,22.15 189.517,21.688 ; 189.055,64.453 189.979,64.453 ; 189.055,64.453 189.517,63.991 ; 189.517,21.688 189.979,22.15 ; 189.517,63.991 189.979,64.453
  BottomLayer w0.5: v1(137.225,78.233) 137.241,78.217 v1(137.241,64.402) v1(137.241,52.806) 137.225,52.789 v1(137.225,35.777) 137.241,35.761 v1(137.241,22.098) v1(137.241,10.35)
  BottomLayer w0.6: v1(145.067,78.233) 145.083,78.217 v1(145.083,64.453) v1(145.083,52.806) 145.067,52.789 v1(145.067,35.777) 145.083,35.761 v1(145.083,22.15) v1(145.083,10.35) ; v1(185.561,78.233) v1(185.561,64.453) 185.561,52.822 v1(185.578,52.806) 185.578,35.794 v1(185.561,35.777) v1(185.561,22.15) 185.561,10.366 v1(185.578,10.35) ; v1(193.403,78.233) v1(193.403,64.453) 193.403,52.822 v1(193.419,52.806) 193.419,35.794 v1(193.403,35.777) v1(193.403,22.15) 193.403,10.366 v1(193.419,10.35)
ADC0: P9.39 R100.1 | length 14.6
  TopLayer w0.3: v2(8.255,32.045) 9.55,30.75 14.232,30.75 15.938,29.044 15.938,27.062 17.264,25.736 R100.1@19.046,25.736
ADC1: P9.40 R101.1 | length 8.4
  TopLayer w0.3: P9.40@12.325,32.045 14.345,32.045 18.346,28.045 R101.1@19.046,28.045
  other v2: 10.795,32.045
ADC2: P9.37 R102.1 | length 12.5
  TopLayer w0.3: v2(8.255,34.585) 9.54,33.3 14.855,33.3 17.802,30.353 R102.1@19.046,30.353
ADC3: P9.38 R103.1 | length 7.5
  TopLayer w0.3: P9.38@12.325,34.585 15.865,34.585 17.789,32.661 R103.1@19.046,32.661
  other v2: 10.795,34.585
ADC4: P9.33 R104.1 | length 11.8
  TopLayer w0.3: v2(8.255,39.665) 9.545,38.375 15.65,38.375 16.861,39.586 R104.1@19.046,39.586
ADC5: P9.36 R105.1 | length 6.8
  TopLayer w0.3: P9.36@12.325,37.125 18.894,37.125 R105.1@19.046,37.277
  other v2: 10.795,37.125
ADC6: P9.35 R106.1 | length 11.7
  TopLayer w0.3: v2(8.255,37.125) 9.53,35.85 16.224,35.85 17.105,34.969 R106.1@19.046,34.969
BBB3V: C17.1 C18.1 C19.1 P4.2 P9.3 P9.4 R97.2 R98.2 R124.1 R124.2 R131.2 U1.20 U2.24 U3.16 U4.1 | length 255.7
  TopLayer w0.35: 111.005,52.455 U2.24@111.005,54.159
  TopLayer w0.5: U3.16@38.139,39.929 C18.1@41.416,39.929 v1(41.416,41.325) ; U4.1@38.139,47.041 C19.1@41.456,47.041 ; v1(41.402,45.624) 41.456,45.679 C19.1@41.456,47.041 ; C19.1@41.456,47.082 C19.1@41.456,47.041 ; C19.1@41.515,47.041 C19.1@41.456,47.041
  TopLayer w0.6: P9.3@6.725,77.765 v2(8.255,77.765) v2(10.795,77.765) P9.4@12.325,77.765 12.375,77.815 14.248,77.815 18.211,81.778 18.909,81.778 R124.1@19.046,81.915 R124.2@20.746,81.915 34.665,81.915 v1(34.675,81.925) ; v1(41.7,84.55) 92.822,84.55 v1(92.836,84.565) ; U1.20@88.264,62.788 C17.1@91.135,62.788 91.135,63.995 91.815,64.675 v1(92.85,64.675) ; v1(92.835,49.6) R97.2@92.835,51.317 ; v1(103.7,46.05) 103.705,46.055 R98.2@103.705,47.464 ; 111.005,52.455 111.005,49.79 v1(112.364,48.431)
  BottomLayer w0.6: P4.2@38.1,5.703 38.1,24.675 41.416,27.991 v1(41.416,41.325) 41.416,45.61 v1(41.402,45.624) 34.725,52.3 34.725,81.875 v1(34.675,81.925) 37.3,84.55 v1(41.7,84.55) ; v1@92.85,84.565 v1(92.85,64.675) 92.85,49.615 v1(92.835,49.6) 92.835,46.806 93.591,46.05 v1(103.7,46.05) 103.7,45.969 103.85,45.819 103.85,45.75 105.275,44.325 110.388,44.325 112.364,46.3 v1(112.364,48.431)
BBB5V: P9.7 P9.8 R127.2 | length 14.1
  TopLayer w0.6: P9.7@6.725,72.685 v2(8.255,72.685) v2(10.795,72.685) P9.8@12.325,72.685 12.453,72.814 14.157,72.814 18.416,77.072 R127.2@19.046,77.072
BBB_5V: C20.1 C21.1 D03.2 IC5.4 IC5.5 IC5.10 IC5.12 R125.1 R127.1 R132.2 | length 126.8
  TopLayer w0.5: IC5.5@31.417,20.147 37.407,20.147 IC5.10@37.417,20.137 C21.1@40.566,20.137 40.566,18.588 40.566,14.781 D03.2@40.665,14.681 ; IC5.4@31.417,21.417 33.467,21.417 34.727,22.677 IC5.12@37.417,22.677 40.494,22.677 C20.1@40.566,22.606 v1@40.566,21.392
  TopLayer w0.6: R127.1@20.746,77.072 R125.1@20.746,79.494 38.119,79.494 38.996,80.371 R132.2@38.996,81.929 40.596,81.929 v1(40.6,81.925) ; D03.2@40.665,14.681 40.709,14.638 v1(43.638,14.638)
  BottomLayer w0.6: v1(40.6,81.925) 37.625,78.95 37.625,52.075 42.975,46.725 42.975,27 40.564,24.589 v1(40.564,21.392) 40.564,18.595 v1(40.571,18.588) 40.571,16.004 41.896,14.679 43.596,14.679 v1(43.638,14.638)
BBB_5V_2A: P9.5 P9.6 R125.2 | length 12.6
  TopLayer w0.6: P9.5@6.725,75.225 v2(8.255,75.225) v2(10.795,75.225) ; P9.6@12.325,75.225 12.382,75.282 14.182,75.282 18.394,79.494 R125.2@19.046,79.494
